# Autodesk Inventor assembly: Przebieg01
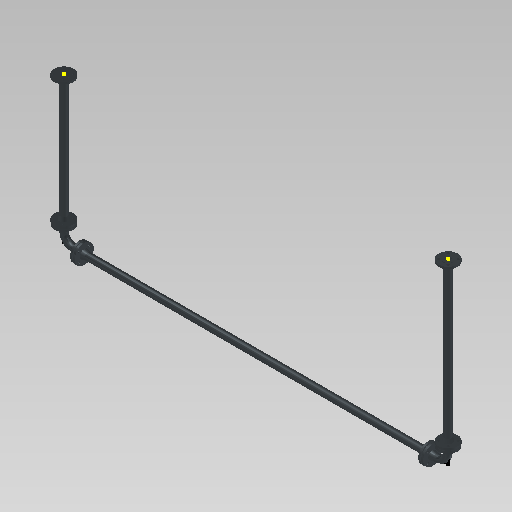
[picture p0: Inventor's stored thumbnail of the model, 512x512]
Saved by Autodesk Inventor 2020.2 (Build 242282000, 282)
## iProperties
Manager: www.cadconsulting.pl
Company: Fabian Stasiak CAD Consulting
Name: ISO 2531 - Rury żelazne kołnierzowe i łączniki
ActiveState: True
PipeType: Rigid Pipe
Material: UnInitValue
Standard: UnInitValue
FittingMaterial: UnInitValue
FittingStandard: UnInitValue
RouteDirection90: True
RouteDirection45: True
IsFlanged: False
IsButtWelded: False
DiameterType: Nominal
Diameter: M40
Schedule: PN10
OD: UnInitValue
ID: UnInitValue
Ending: UnInitValue
IntermediateSegmentsMin: 1000,000 mm
IntermediateSegmentsMax: 9000,000 mm
IntermediateSegmentsInc: 10,000 mm
TerminationSegmentsMin: 1000,000 mm
TerminationSegmentsMax: 9000,000 mm
TerminationSegmentsInc: 10,000 mm
RoundUpValue: UnInitValue
PipingComponentColor: As Material
PipeKey: v3#f52fbdcb-ece8-4303-8b76-5dbe8c7f2f9c#16
Elbow90Key: v3#451ae64e-c79d-4cba-b533-c09b8090ecb2#1
Elbow45Key: v3#81684a3f-f2a4-4fe6-95b1-f067ddead22f#1
FlangeKey: UnInitValue
GasketKey: UnInitValue
Gap: UnInitValue
_ComponentInfo: <CS><C N="Pipe" R="2.700000" IR="2.000000" PL="PL" PN="ISO 2531 Pipe with Integrally Cast Flanges DN40 PN 10"><CO N="1"><FE V="0"/><FD V="0"/><ET V="Flanged"/><
ShowGap: UnInitValue
MixedUnits: False
UseFlangsForCouplings: UnInitValue
IsSelfDraining: False
ElbowCustomKey: UnInitValue
Created: 2014-08
Part Number: Przebieg01
Document SubType Name: Assembly
Designer: F.Stasiak
Catalog Web Link: www.expertbooks.pl
Author: F.Stasiak
Subject: Zbiór ćwiczeń. Autodesk Inventor 2020. Kurs Professional
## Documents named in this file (6)
- C:\2020_Kurs_Professional\R1 Rury\Redagowanie_test_1\AIP\Przewody rurowe\Przebieg01\Redagowanie_test_1.Przebieg01.iam
- C:\2020_Kurs_Professional\R1 Rury\Redagowanie_test_1\AIP\Przewody rurowe\Przebieg01\Redagowanie_test_1.Trasa01.ipt
- C:\2020_Kurs_Professional\R1 Rury\Redagowanie_test_1\AIP\Przewody rurowe\Przebieg01\pipipe.1409147186131.ipt
- C:\2020_Kurs_Professional\R1 Rury\Redagowanie_test_1\AIP\Przewody rurowe\Przebieg01\pipipe.1409147186770.ipt
- C:\2020_Kurs_Professional\R1 Rury\Redagowanie_test_1\AIP\Przewody rurowe\Przebieg01\pipipe.1409147186851.ipt
- C:\2020_Kurs_Professional\Zasoby\ContentCenter\pl-PL\ISO 2531 90 - PN 10\ISO 2531 Double-flanged 90deg(1_4) bends - PN 10 DN40.ipt
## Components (6 placed, 5 different names)
1. Trasa01
2. Segment rurowy 1:1
3. ISO 2531 Łuki 90° (1/4) dwukołnierzowe, szereg A - PN 10 DN40:1
4. Segment rurowy 2:1
5. ISO 2531 Łuki 90° (1/4) dwukołnierzowe, szereg A - PN 10 DN40:2
6. Segment rurowy 3:1
